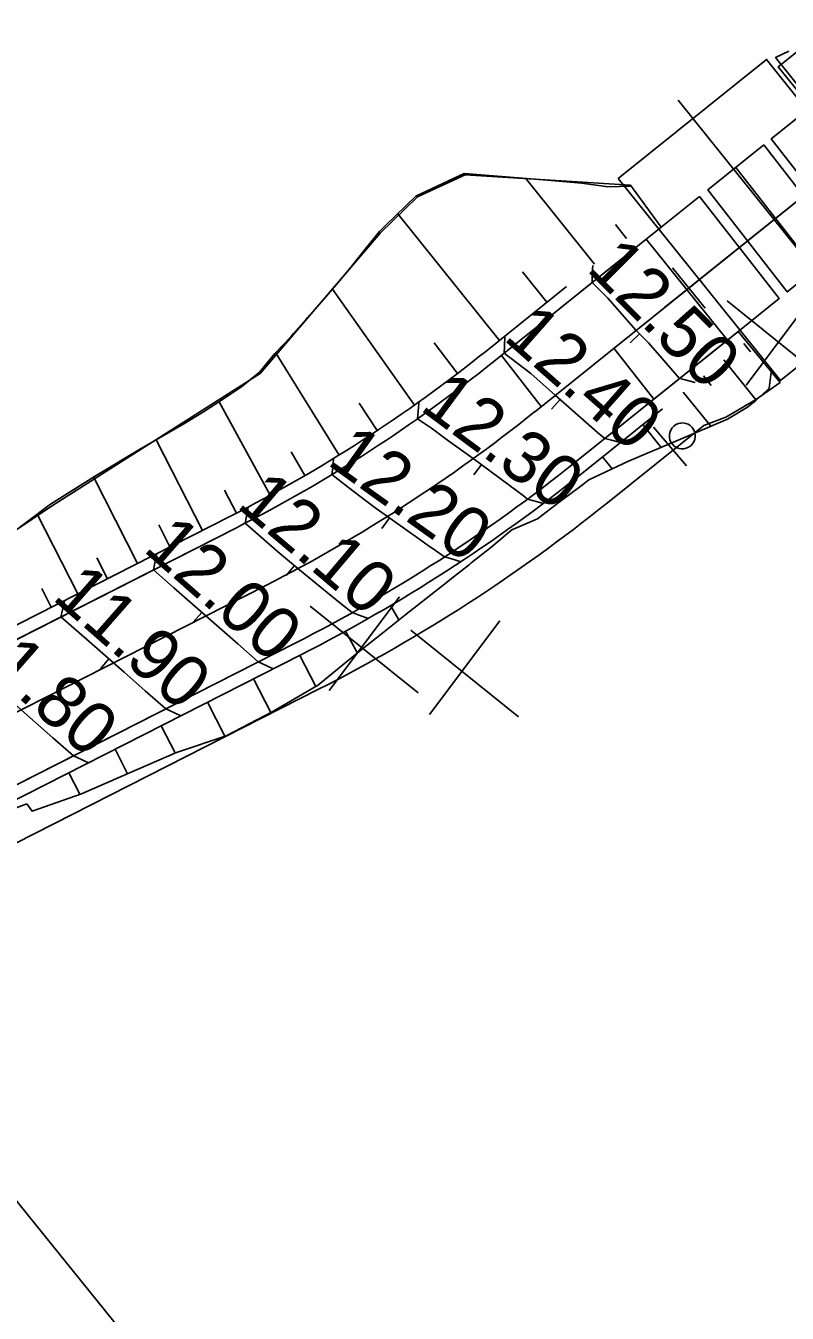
# Model space of a CAD drawing. Extents: x 554247.5 to 554326.1, y 6593477.6 to 6593537.1.
# Drawn here: x 554281.38 to 554296.08, y 6593498.07 to 6593522.92 of the extents above; entities that cross this region are included whole.
import ezdxf

# ---------------------------------------------------------------- set-up
doc = ezdxf.new("R2010")
doc.units = 0
for name, color, linetype in [('ASF', 7, 'Continuous'), ('BETOON', 7, 'Continuous'), ('FILL ASF KT', 7, 'Continuous'), ('FILL ROHELINE', 7, 'Continuous'), ('KRAAV PUHASTAMINE', 7, 'Continuous'), ('LIIKLUSMÄRK', 7, 'Continuous'), ('LIKV', 7, 'Continuous'), ('NÕLV', 7, 'Continuous'), ('PIIRE TÕKKEPUU', 7, 'Continuous'), ('PK', 7, 'Continuous'), ('TELG', 7, 'Continuous'), ('VERT', 7, 'Continuous')]:
    doc.layers.add(name, color=color, linetype=linetype)

msp = doc.modelspace()

# ---------------------------------------------------------------- linework, layer by layer
at = {"layer": 'ASF'}
for points in [[(554290.413, 6593516.439), (554293.355, 6593518.8), (554294.92, 6593516.851)], [(554294.92, 6593516.851), (554291.978, 6593514.489)], [(554264.161, 6593502.412), (554285.444, 6593513.231)], [(554286.577, 6593511.002), (554266.083, 6593500.584)]]:
    msp.add_lwpolyline(points, dxfattribs=at)
for radius in [28.75, 31.25]:
    msp.add_arc((554272.416, 6593538.86), radius, 296.9456, 308.7536, dxfattribs=at)
at = {"layer": 'BETOON'}
for points in [[(554292.815, 6593519.97), (554295.679, 6593522.269), (554298.802, 6593518.364), (554295.944, 6593516.07)], [(554296.724, 6593521.505), (554298.289, 6593519.555), (554297.304, 6593518.765), (554295.767, 6593520.736)], [(554295.622, 6593520.62), (554297.159, 6593518.648), (554296.078, 6593517.781), (554294.541, 6593519.752)], [(554294.381, 6593519.624), (554295.919, 6593517.653), (554294.92, 6593516.851), (554293.355, 6593518.8)]]:
    msp.add_lwpolyline(points, close=True, dxfattribs=at)
msp.add_lwpolyline([(554295.081, 6593520.186), (554298.344, 6593516.002)], dxfattribs=at)
at = {"layer": 'FILL ASF KT'}
for p, q in [((554291.978, 6593514.489), (554294.92, 6593516.851)), ((554285.444, 6593513.231), (554264.161, 6593502.412)), ((554266.083, 6593500.584), (554286.577, 6593511.002))]:
    msp.add_line(p, q, dxfattribs=at)
msp.add_lwpolyline([(554294.92, 6593516.851), (554293.355, 6593518.8), (554290.413, 6593516.439)], dxfattribs=at)
for radius in [28.75, 31.25]:
    msp.add_arc((554272.416, 6593538.86), radius, 296.9456, 308.7536, dxfattribs=at)
at = {"layer": 'FILL ROHELINE'}
for p, q in [((554286.577, 6593511.002), (554266.083, 6593500.584)), ((554266.536, 6593499.693), (554287.03, 6593510.111))]:
    msp.add_line(p, q, dxfattribs=at)
for points in [[(554298.589, 6593524.284), (554295.903, 6593522.128), (554296.529, 6593521.349)], [(554298.589, 6593524.284), (554295.903, 6593522.128), (554296.529, 6593521.349)], [(554277.854, 6593510.768), (554278.526, 6593511.403), (554281.872, 6593513.649), (554285.905, 6593516.209), (554288.219, 6593518.918), (554288.941, 6593519.616), (554289.857, 6593520.042), (554293.053, 6593519.84), (554293.641, 6593519.03), (554290.413, 6593516.439)], [(554290.413, 6593516.439), (554293.641, 6593519.03), (554293.053, 6593519.84), (554289.857, 6593520.042), (554288.941, 6593519.616), (554288.219, 6593518.918), (554285.905, 6593516.209), (554281.872, 6593513.649), (554278.526, 6593511.403), (554277.854, 6593510.768)], [(554291.978, 6593514.489), (554295.13, 6593517.019), (554295.94, 6593516.031)], [(554295.94, 6593516.031), (554295.13, 6593517.019), (554291.978, 6593514.489)], [(554295.94, 6593516.031), (554295.464, 6593515.699), (554294.892, 6593515.367), (554294.467, 6593515.205), (554292.604, 6593513.71)], [(554292.604, 6593513.71), (554294.467, 6593515.205), (554294.892, 6593515.367), (554295.464, 6593515.699), (554295.94, 6593516.031)], [(554285.444, 6593513.231), (554278.724, 6593509.815), (554277.854, 6593510.768)], [(554277.854, 6593510.768), (554278.724, 6593509.815), (554285.444, 6593513.231)], [(554266.083, 6593500.584), (554286.577, 6593511.002)], [(554287.03, 6593510.111), (554266.536, 6593499.693)]]:
    msp.add_lwpolyline(points, dxfattribs=at)
for radius in [28.75, 28.75, 31.25, 31.25, 32.25, 32.25]:
    msp.add_arc((554272.416, 6593538.86), radius, 296.9456, 308.7536, dxfattribs=at)
at = {"layer": 'KRAAV PUHASTAMINE'}
msp.add_lwpolyline([(554289.368, 6593490.108), (554278.553, 6593503.507)], dxfattribs=at)
at = {"layer": 'LIIKLUSMÄRK'}
msp.add_lwpolyline([(554294.134, 6593514.425), (554293.494, 6593515.173)], dxfattribs=at)
for start, end in [(40.559, 220.559), (40.559, 220.559), (220.559, 40.559), (220.559, 40.559)]:
    msp.add_arc((554294.05, 6593515.003), 0.25, start, end, dxfattribs=at)
at = {"layer": 'LIKV'}
for points in [[(554295.281, 6593515.979), (554296.639, 6593517.788)], [(554294.919, 6593517.607), (554297.001, 6593515.933)], [(554286.87, 6593511.715), (554288.952, 6593510.042)], [(554287.232, 6593510.087), (554288.59, 6593511.896)], [(554289.17, 6593509.624), (554290.528, 6593511.433)], [(554288.808, 6593511.252), (554290.89, 6593509.579)]]:
    msp.add_lwpolyline(points, dxfattribs=at)
at = {"layer": 'NÕLV'}
for p, q in [((554296.429, 6593521.589), (554295.851, 6593522.308)), ((554292.355, 6593518.318), (554291.028, 6593519.971)), ((554290.52, 6593516.846), (554288.557, 6593519.292)), ((554292.975, 6593518.816), (554292.762, 6593519.081)), ((554291.437, 6593517.582), (554290.966, 6593518.17)), ((554288.884, 6593515.599), (554287.299, 6593517.838)), ((554289.712, 6593516.208), (554289.261, 6593516.8)), ((554295.24, 6593516.787), (554295.369, 6593516.626)), ((554287.428, 6593514.634), (554286.201, 6593516.614)), ((554294.85, 6593516.474), (554295.479, 6593515.691)), ((554294.46, 6593516.161), (554294.61, 6593515.973)), ((554286.095, 6593513.857), (554285.108, 6593515.662)), ((554288.163, 6593515.105), (554287.812, 6593515.635)), ((554294.07, 6593515.848), (554294.599, 6593515.189)), ((554293.29, 6593515.222), (554293.643, 6593514.782)), ((554284.787, 6593513.177), (554283.896, 6593514.93)), ((554286.766, 6593514.237), (554286.499, 6593514.697)), ((554292.51, 6593514.596), (554292.695, 6593514.366)), ((554283.534, 6593512.54), (554282.685, 6593514.211)), ((554285.444, 6593513.512), (554285.214, 6593513.958)), ((554282.381, 6593511.954), (554281.599, 6593513.492)), ((554284.161, 6593512.859), (554283.943, 6593513.287)), ((554282.957, 6593512.247), (554282.752, 6593512.651)), ((554281.87, 6593511.694), (554281.686, 6593512.057)), ((554288.42, 6593511.729), (554288.582, 6593511.455)), ((554287.551, 6593511.234), (554287.782, 6593510.812)), ((554286.667, 6593510.767), (554286.974, 6593510.164)), ((554285.775, 6593510.314), (554286.107, 6593509.661)), ((554284.884, 6593509.861), (554285.217, 6593509.206)), ((554283.992, 6593509.408), (554284.26, 6593508.882)), ((554283.101, 6593508.955), (554283.341, 6593508.483)), ((554282.21, 6593508.502), (554282.421, 6593508.086))]:
    msp.add_line(p, q, dxfattribs=at)
for points in [[(554295.851, 6593522.308), (554296.109, 6593522.43)], [(554281.041, 6593513.075), (554281.854, 6593513.683), (554282.702, 6593514.221), (554283.562, 6593514.737), (554284.426, 6593515.235), (554284.429, 6593515.237), (554284.806, 6593515.468), (554285.178, 6593515.707), (554285.545, 6593515.953), (554285.891, 6593516.233), (554286.183, 6593516.595), (554286.496, 6593516.915), (554286.544, 6593516.979), (554286.79, 6593517.257), (554286.811, 6593517.281), (554287.085, 6593517.59), (554287.374, 6593517.927), (554287.656, 6593518.266), (554287.931, 6593518.609), (554288.206, 6593518.947), (554288.313, 6593519.056), (554288.905, 6593519.63), (554289.837, 6593520.067), (554291.208, 6593519.957), (554291.819, 6593519.907), (554292.106, 6593519.879), (554292.528, 6593519.823), (554292.608, 6593519.81), (554293.068, 6593519.82)], [(554281.395, 6593507.898), (554281.5, 6593507.758), (554282.451, 6593508.096), (554283.369, 6593508.495), (554284.288, 6593508.894), (554285.247, 6593509.216), (554286.135, 6593509.676), (554286.997, 6593510.177), (554287, 6593510.18), (554287.425, 6593510.524), (554287.847, 6593510.865), (554288.267, 6593511.204), (554288.686, 6593511.539), (554289.106, 6593511.867), (554289.524, 6593512.195), (554289.596, 6593512.252), (554289.941, 6593512.522), (554289.97, 6593512.545), (554290.356, 6593512.848), (554290.76, 6593513.189), (554291.258, 6593513.4), (554291.677, 6593513.721), (554292.096, 6593514.042), (554292.246, 6593514.156), (554293.012, 6593514.514), (554293.968, 6593514.92), (554294.924, 6593515.327), (554295.308, 6593515.56), (554295.472, 6593515.685), (554295.69, 6593515.883), (554295.729, 6593515.922), (554295.774, 6593516.282)], [(554273.557, 6593503.889), (554274.342, 6593504.186), (554275.491, 6593504.132), (554276.61, 6593504.138), (554277.723, 6593504.155), (554278.137, 6593504.308), (554278.168, 6593504.382), (554278.425, 6593504.982), (554278.682, 6593505.579), (554278.94, 6593506.175), (554279.21, 6593506.747), (554279.617, 6593507.049), (554280.034, 6593507.333), (554280.482, 6593507.555), (554280.936, 6593507.729), (554281.395, 6593507.898)]]:
    msp.add_lwpolyline(points, dxfattribs=at)
at = {"layer": 'PIIRE TÕKKEPUU'}
for points in [[(554290.257, 6593516.634), (554291.816, 6593517.886)], [(554293.499, 6593515.711), (554292.73, 6593516.696)], [(554291.326, 6593515.57), (554290.558, 6593516.555)], [(554293.671, 6593515.527), (554292.134, 6593514.294)], [(554265.258, 6593503.25), (554285.331, 6593513.454)], [(554286.69, 6593510.779), (554266.196, 6593500.361)]]:
    msp.add_lwpolyline(points, dxfattribs=at)
for radius in [28.5, 31.5]:
    msp.add_arc((554272.416, 6593538.86), radius, 296.9456, 308.7536, dxfattribs=at)
at = {"layer": 'PK'}
msp.add_line((554294.489, 6593517.467), (554293.863, 6593518.247), dxfattribs=at)
at = {"layer": 'TELG'}
for points in [[(554291.196, 6593515.464), (554299.997, 6593522.529)], [(554293.707, 6593517.48), (554298.559, 6593521.375)], [(554293.97, 6593521.484), (554298.416, 6593515.947)], [(554259.272, 6593498.524), (554286.011, 6593512.116)]]:
    msp.add_lwpolyline(points, dxfattribs=at)
msp.add_arc((554272.416, 6593538.86), 30, 296.9456, 308.7536, dxfattribs=at)
at = {"layer": 'VERT'}
for p, q in [((554293.046, 6593516.799), (554293.223, 6593516.975)), ((554291.526, 6593515.519), (554291.691, 6593515.707)), ((554290.024, 6593514.249), (554290.173, 6593514.449)), ((554288.252, 6593513.216), (554288.397, 6593513.42)), ((554286.403, 6593512.307), (554286.564, 6593512.498)), ((554284.608, 6593511.409), (554284.773, 6593511.597)), ((554282.818, 6593510.509), (554282.983, 6593510.697))]:
    msp.add_line(p, q, dxfattribs=at)
for points in [[(554292.323, 6593518.293), (554292.32, 6593518.22), (554292.31, 6593517.962), (554292.615, 6593517.662), (554293.159, 6593517.04), (554293.397, 6593516.801), (554293.998, 6593516.111), (554294.056, 6593516.095), (554294.298, 6593516.031)], [(554290.625, 6593516.93), (554290.617, 6593516.738), (554290.611, 6593516.598), (554291.125, 6593516.206), (554291.599, 6593515.788), (554292.413, 6593515.071), (554292.556, 6593514.953), (554292.58, 6593514.947), (554292.687, 6593514.918), (554292.83, 6593514.881), (554292.856, 6593514.874)], [(554288.964, 6593515.656), (554288.962, 6593515.624), (554288.939, 6593515.333), (554289.209, 6593515.149), (554289.521, 6593514.923), (554290.016, 6593514.566), (554290.858, 6593513.941), (554290.976, 6593513.853), (554291.064, 6593513.784), (554291.254, 6593513.731), (554291.369, 6593513.7)], [(554287.32, 6593514.568), (554287.302, 6593514.392), (554287.287, 6593514.255), (554287.606, 6593514.004), (554287.936, 6593513.759), (554288.144, 6593513.601), (554288.359, 6593513.447), (554289.027, 6593512.969), (554289.17, 6593512.871), (554289.22, 6593512.835), (554289.462, 6593512.669), (554289.622, 6593512.621), (554289.774, 6593512.574)], [(554285.668, 6593513.629), (554285.639, 6593513.454), (554285.614, 6593513.319), (554286.23, 6593512.781), (554286.631, 6593512.442), (554287.266, 6593511.92), (554287.469, 6593511.754), (554287.679, 6593511.592), (554287.811, 6593511.541), (554287.985, 6593511.476)], [(554283.905, 6593512.729), (554283.883, 6593512.625), (554283.84, 6593512.415), (554284.236, 6593512.068), (554284.852, 6593511.527), (554285.468, 6593510.987), (554285.864, 6593510.64), (554285.936, 6593510.607), (554286.156, 6593510.507)], [(554282.122, 6593511.822), (554282.073, 6593511.586), (554282.057, 6593511.509), (554282.6, 6593511.033), (554283.069, 6593510.621), (554283.274, 6593510.441), (554283.685, 6593510.081), (554284.081, 6593509.733), (554284.152, 6593509.701), (554284.373, 6593509.601)], [(554280.339, 6593510.916), (554280.318, 6593510.813), (554280.274, 6593510.603), (554280.67, 6593510.255), (554281.286, 6593509.715), (554281.902, 6593509.174), (554282.298, 6593508.827), (554282.37, 6593508.795), (554282.59, 6593508.695)]]:
    msp.add_lwpolyline(points, dxfattribs=at)

# ---------------------------------------------------------------- texts
for s, rotation, p in [('12.50', 314.9186, (554292.183, 6593518.214)), ('12.40', 318.5921, (554290.574, 6593516.876)), ('12.30', 323.3838, (554288.962, 6593515.522)), ('12.20', 324.4186, (554287.167, 6593514.47)), ('12.10', 319.7757, (554285.423, 6593513.644)), ('12.00', 318.747, (554283.62, 6593512.797)), ('11.90', 318.747, (554281.865, 6593511.866)), ('11.80', 318.747, (554280.073, 6593510.963))]:
    msp.add_text(s, height=1, rotation=rotation, dxfattribs=at).set_placement(p)

doc.saveas('drawing.dxf')
